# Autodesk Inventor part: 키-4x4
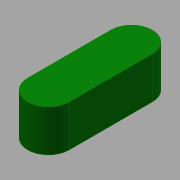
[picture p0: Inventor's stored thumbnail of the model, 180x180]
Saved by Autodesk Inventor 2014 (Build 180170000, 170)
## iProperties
Created: 2015-12
Part Number: 키-4x4
Document SubType Name: Modeling
Designer: mdu
Density: 7.86 g/cm^3
Material: 강철, 연강
Appearance: 진녹색
Mass: 1.40117 g
Surface Area: 2.03398 cm^2
Volume: 0.178265 cm^3
Author: mdu
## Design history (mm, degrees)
sketch "스케치1"
  geometry: L1 (-2, -10)-(-2, -2) reference; L2 (2, -2)-(2, -10) reference; A1 r 2 centre (0, -2) between (2, -2) and (-2, -2) reference; A2 r 2 centre (0, -10) between (-2, -10) and (2, -10) reference; 1 further point
extrude "돌출1" new body sketch "스케치1" distance "d0" = 4; taper "d1" = 0 deg
node "솔리드1"
node "참조1"
